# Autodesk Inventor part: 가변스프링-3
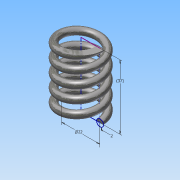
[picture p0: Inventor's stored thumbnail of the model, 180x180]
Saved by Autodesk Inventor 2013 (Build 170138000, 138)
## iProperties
Created: 2016-01
Part Number: 가변스프링-3
Material: 스테인리스강
Document SubType Name: Modeling
Designer: Administrator
Mass: 34.3346 g
Surface Area: 43.3134 cm^2
Volume: 4.24934 cm^3
Density: 8.08 g/cm^3
Author: Administrator
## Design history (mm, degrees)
sketch "스케치1"
  geometry: L1 (0, 0)-(11, 0); L2 (11, 0)-(11, 36.411); L3 (11, 36.411)-(0, 36.411); L4 (0, 36.411)-(0, 0); C1 r 2 at (11, 0)
  constraints: 8 end point, 2 parallel, 1 centre point, 1 coincident, 1 horizontal, 1 perpendicular
  dimensions: "d0" = 2 radius of C1; "d1" = 22 diameter of L2 L4; "d2" = 36.4112 distance between parallel lines of L3 L1 (derived)
feature "코일1" sketch "스케치1" pitch "d3" = 10; turns "d5" = 5; dims "d4" = 36.4112 (= d2), "d6" = 0, angle "d7" = 90 deg, angle "d8" = 90 deg, "d9" = 0, "d10" = 0
feature "분할1"
node "작업 평면1"
feature "분할2"
node "솔리드1"
other parameters: "d11" = 90 deg
